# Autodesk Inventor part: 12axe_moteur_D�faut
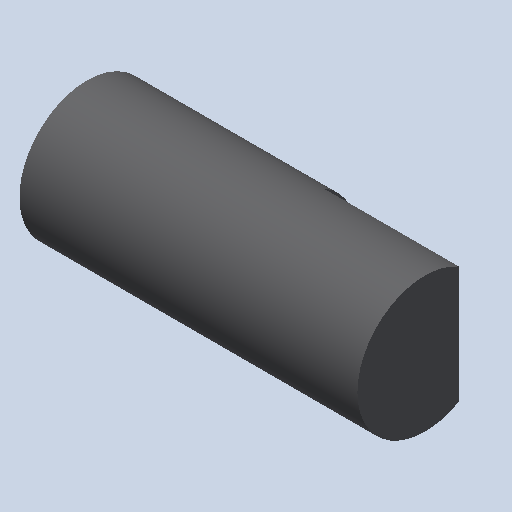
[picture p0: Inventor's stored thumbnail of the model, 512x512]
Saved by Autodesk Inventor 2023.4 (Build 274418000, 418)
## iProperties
Created: 2011-01
Part Number: 12axe_moteur_D�faut
Document SubType Name: Modeling
Designer: eric
Density: 1 g/cm^3
Mass: 0.926695 g
Surface Area: 5.91591 cm^2
Volume: 0.926695 cm^3
Material: Générique
Appearance: Yellow
Author: eric
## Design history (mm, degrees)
feature "Base1"
node "Corps solides"
node "Corps surfaciques"
node "Solide1"
